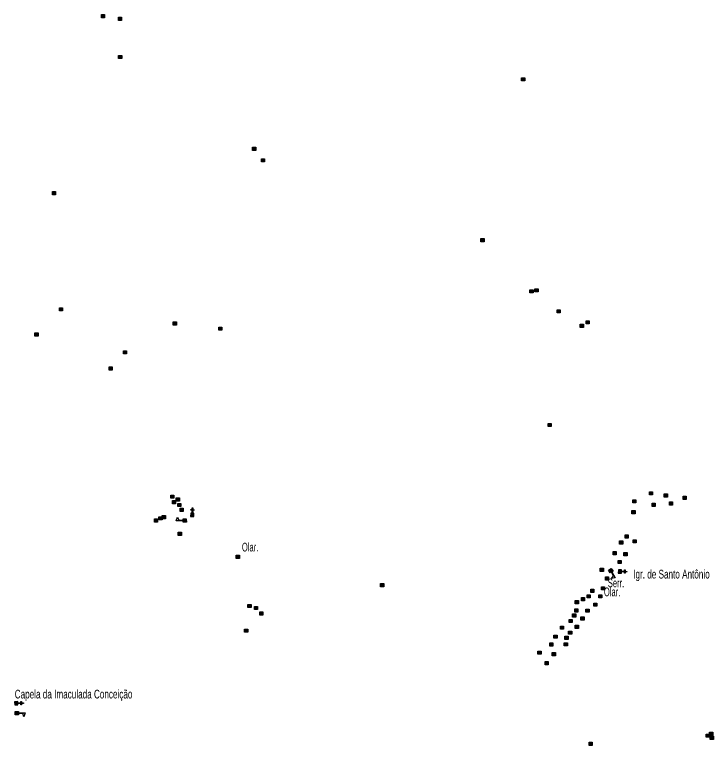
# Model space of a CAD drawing. Extents: x 647.8 to 672.9, y 6929.3 to 6957.3.
# Drawn here: x 653.69 to 660.11, y 6929.64 to 6936.36 of the extents above; entities that cross this region are included whole.
import ezdxf

# ---------------------------------------------------------------- set-up
doc = ezdxf.new("R2010")
doc.units = 0
doc.header["$LTSCALE"] = 0.032
for name, color, linetype, lineweight in [('2', 7, 'Continuous', 25), ('4', 7, 'Continuous', 25), ('6', 7, 'Continuous', 25)]:
    doc.layers.add(name, color=color, linetype=linetype, lineweight=lineweight)
doc.layers.add('61', color=7, linetype='Continuous')

msp = doc.modelspace()

# ---------------------------------------------------------------- hatches: boundary and pattern name
at = {"layer": '2'}
for points in [[(654.4867, 6936.3644), (654.5157, 6936.3644), (654.5157, 6936.3354), (654.4867, 6936.3354)], [(654.6425, 6936.3403), (654.6715, 6936.3403), (654.6715, 6936.3113), (654.6425, 6936.3113)], [(654.6447, 6935.9893), (654.6737, 6935.9893), (654.6737, 6935.9603), (654.6447, 6935.9603)], [(658.3501, 6935.7831), (658.3791, 6935.7831), (658.3791, 6935.7541), (658.3501, 6935.7541)], [(655.8776, 6935.1447), (655.9066, 6935.1447), (655.9066, 6935.1157), (655.8776, 6935.1157)], [(655.9588, 6935.0394), (655.9878, 6935.0394), (655.9878, 6935.0104), (655.9588, 6935.0104)], [(654.037, 6934.7366), (654.066, 6934.7366), (654.066, 6934.7076), (654.037, 6934.7076)], [(657.9771, 6934.3044), (658.0061, 6934.3044), (658.0061, 6934.2754), (657.9771, 6934.2754)], [(658.4729, 6933.8437), (658.5019, 6933.8437), (658.5019, 6933.8147), (658.4729, 6933.8147)], [(658.4269, 6933.8349), (658.4559, 6933.8349), (658.4559, 6933.8059), (658.4269, 6933.8059)], [(654.1006, 6933.6682), (654.1296, 6933.6682), (654.1296, 6933.6392), (654.1006, 6933.6392)], [(658.677, 6933.6507), (658.706, 6933.6507), (658.706, 6933.6217), (658.677, 6933.6217)], [(655.1471, 6933.5388), (655.1761, 6933.5388), (655.1761, 6933.5098), (655.1471, 6933.5098)], [(658.8898, 6933.5168), (658.9188, 6933.5168), (658.9188, 6933.4878), (658.8898, 6933.4878)], [(658.9446, 6933.5497), (658.9736, 6933.5497), (658.9736, 6933.5207), (658.9446, 6933.5207)], [(653.8746, 6933.4379), (653.9036, 6933.4379), (653.9036, 6933.4089), (653.8746, 6933.4089)], [(655.5661, 6933.4905), (655.5951, 6933.4905), (655.5951, 6933.4615), (655.5661, 6933.4615)], [(654.6886, 6933.2733), (654.7176, 6933.2733), (654.7176, 6933.2443), (654.6886, 6933.2443)], [(654.5569, 6933.1241), (654.5859, 6933.1241), (654.5859, 6933.0951), (654.5569, 6933.0951)], [(658.5936, 6932.6042), (658.6226, 6932.6042), (658.6226, 6932.5752), (658.5936, 6932.5752)], [(659.526, 6931.9768), (659.555, 6931.9768), (659.555, 6931.9478), (659.526, 6931.9478)], [(659.662, 6931.957), (659.691, 6931.957), (659.691, 6931.928), (659.662, 6931.928)], [(655.1251, 6931.946), (655.1541, 6931.946), (655.1541, 6931.917), (655.1251, 6931.917)], [(655.1405, 6931.8956), (655.1695, 6931.8956), (655.1695, 6931.8666), (655.1405, 6931.8666)], [(655.1756, 6931.9197), (655.2046, 6931.9197), (655.2046, 6931.8907), (655.1756, 6931.8907)], [(659.3724, 6931.9022), (659.4014, 6931.9022), (659.4014, 6931.8732), (659.3724, 6931.8732)], [(659.8353, 6931.9351), (659.8643, 6931.9351), (659.8643, 6931.9061), (659.8353, 6931.9061)], [(655.1888, 6931.8693), (655.2178, 6931.8693), (655.2178, 6931.8403), (655.1888, 6931.8403)], [(655.2107, 6931.8254), (655.2397, 6931.8254), (655.2397, 6931.7964), (655.2107, 6931.7964)], [(659.5501, 6931.8714), (659.5791, 6931.8714), (659.5791, 6931.8424), (659.5501, 6931.8424)], [(659.7103, 6931.8824), (659.7393, 6931.8824), (659.7393, 6931.8534), (659.7103, 6931.8534)], [(655.0462, 6931.7574), (655.0752, 6931.7574), (655.0752, 6931.7284), (655.0462, 6931.7284)], [(659.3658, 6931.8034), (659.3948, 6931.8034), (659.3948, 6931.7744), (659.3658, 6931.7744)], [(654.9738, 6931.7267), (655.0028, 6931.7267), (655.0028, 6931.6977), (654.9738, 6931.6977)], [(655.0154, 6931.7464), (655.0444, 6931.7464), (655.0444, 6931.7174), (655.0154, 6931.7174)], [(655.1931, 6931.6038), (655.2221, 6931.6038), (655.2221, 6931.5748), (655.1931, 6931.5748)], [(659.3022, 6931.5797), (659.3312, 6931.5797), (659.3312, 6931.5507), (659.3022, 6931.5507)], [(659.2518, 6931.5248), (659.2808, 6931.5248), (659.2808, 6931.4958), (659.2518, 6931.4958)], [(659.3768, 6931.5358), (659.4058, 6931.5358), (659.4058, 6931.5068), (659.3768, 6931.5068)], [(659.1925, 6931.4261), (659.2215, 6931.4261), (659.2215, 6931.3971), (659.1925, 6931.3971)], [(659.2916, 6931.4175), (659.3206, 6931.4175), (659.3206, 6931.3885), (659.2916, 6931.3885)], [(655.7263, 6931.3932), (655.7553, 6931.3932), (655.7553, 6931.3642), (655.7263, 6931.3642)], [(659.2386, 6931.3449), (659.2676, 6931.3449), (659.2676, 6931.3159), (659.2386, 6931.3159)], [(659.0741, 6931.2725), (659.1031, 6931.2725), (659.1031, 6931.2435), (659.0741, 6931.2435)], [(659.1223, 6931.1935), (659.1513, 6931.1935), (659.1513, 6931.1645), (659.1223, 6931.1645)], [(657.0535, 6931.1321), (657.0825, 6931.1321), (657.0825, 6931.1031), (657.0535, 6931.1031)], [(659.085, 6931.1036), (659.114, 6931.1036), (659.114, 6931.0746), (659.085, 6931.0746)], [(658.9534, 6931.029), (658.9824, 6931.029), (658.9824, 6931), (658.9534, 6931)], [(658.9863, 6931.0795), (659.0153, 6931.0795), (659.0153, 6931.0505), (658.9863, 6931.0505)], [(659.0609, 6931.029), (659.0899, 6931.029), (659.0899, 6931), (659.0609, 6931)], [(658.8437, 6930.9764), (658.8727, 6930.9764), (658.8727, 6930.9474), (658.8437, 6930.9474)], [(658.9007, 6931.0027), (658.9297, 6931.0027), (658.9297, 6930.9737), (658.9007, 6930.9737)], [(659.0148, 6930.9522), (659.0438, 6930.9522), (659.0438, 6930.9232), (659.0148, 6930.9232)], [(655.8337, 6930.9413), (655.8627, 6930.9413), (655.8627, 6930.9123), (655.8337, 6930.9123)], [(655.893, 6930.9215), (655.922, 6930.9215), (655.922, 6930.8925), (655.893, 6930.8925)], [(658.8393, 6930.8996), (658.8683, 6930.8996), (658.8683, 6930.8706), (658.8393, 6930.8706)], [(658.9424, 6930.8974), (658.9714, 6930.8974), (658.9714, 6930.8684), (658.9424, 6930.8684)], [(655.9434, 6930.8711), (655.9724, 6930.8711), (655.9724, 6930.8421), (655.9434, 6930.8421)], [(658.8196, 6930.8535), (658.8486, 6930.8535), (658.8486, 6930.8245), (658.8196, 6930.8245)], [(658.8964, 6930.825), (658.9254, 6930.825), (658.9254, 6930.796), (658.8964, 6930.796)], [(658.7867, 6930.803), (658.8157, 6930.803), (658.8157, 6930.774), (658.7867, 6930.774)], [(658.8437, 6930.7482), (658.8727, 6930.7482), (658.8727, 6930.7192), (658.8437, 6930.7192)], [(655.803, 6930.7131), (655.832, 6930.7131), (655.832, 6930.6841), (655.803, 6930.6841)], [(658.7077, 6930.7416), (658.7367, 6930.7416), (658.7367, 6930.7126), (658.7077, 6930.7126)], [(658.7823, 6930.6955), (658.8113, 6930.6955), (658.8113, 6930.6665), (658.7823, 6930.6665)], [(658.6485, 6930.6583), (658.6775, 6930.6583), (658.6775, 6930.6293), (658.6485, 6930.6293)], [(658.7494, 6930.6473), (658.7784, 6930.6473), (658.7784, 6930.6183), (658.7494, 6930.6183)], [(658.609, 6930.5859), (658.638, 6930.5859), (658.638, 6930.5569), (658.609, 6930.5569)], [(658.7428, 6930.588), (658.7718, 6930.588), (658.7718, 6930.559), (658.7428, 6930.559)], [(658.5015, 6930.5113), (658.5305, 6930.5113), (658.5305, 6930.4823), (658.5015, 6930.4823)], [(658.6331, 6930.4981), (658.6621, 6930.4981), (658.6621, 6930.4691), (658.6331, 6930.4691)], [(658.5673, 6930.4147), (658.5963, 6930.4147), (658.5963, 6930.3857), (658.5673, 6930.3857)], [(660.0481, 6929.7478), (660.0771, 6929.7478), (660.0771, 6929.7188), (660.0481, 6929.7188)], [(660.0788, 6929.7654), (660.1078, 6929.7654), (660.1078, 6929.7364), (660.0788, 6929.7364)], [(658.9709, 6929.6732), (658.9999, 6929.6732), (658.9999, 6929.6442), (658.9709, 6929.6442)], [(660.0854, 6929.7281), (660.1144, 6929.7281), (660.1144, 6929.6991), (660.0854, 6929.6991)]]:
    msp.add_hatch(color=256, dxfattribs=at).paths.add_polyline_path(points)
at = {"layer": '4'}
for points in [[(655.2679, 6931.6973), (655.2379, 6931.697), (655.2376, 6931.727), (655.2676, 6931.7273)], [(659.1759, 6931.2717), (659.1913, 6931.2459), (659.1655, 6931.2306), (659.1501, 6931.2564)], [(653.6935, 6929.9544), (653.7234, 6929.9549), (653.7239, 6929.9249), (653.6939, 6929.9244)]]:
    msp.add_hatch(color=256, dxfattribs=at).paths.add_polyline_path(points)
at = {"layer": '6'}
for points in [[(655.3251, 6931.7795), (655.3201, 6931.7797), (655.3216, 6931.8072), (655.309, 6931.8079), (655.3093, 6931.8129), (655.3218, 6931.8122), (655.3227, 6931.8297), (655.3277, 6931.8294), (655.3267, 6931.8119), (655.3393, 6931.8113), (655.339, 6931.8063), (655.3265, 6931.8069)], [(655.3076, 6931.7804), (655.3061, 6931.7505), (655.336, 6931.7489), (655.3375, 6931.7788)], [(659.2704, 6931.2582), (659.2404, 6931.2589), (659.2397, 6931.2289), (659.2697, 6931.2282)], [(659.27, 6931.2407), (659.2701, 6931.2457), (659.2976, 6931.2451), (659.2979, 6931.2576), (659.3029, 6931.2575), (659.3026, 6931.245), (659.3201, 6931.2446), (659.32, 6931.2396), (659.3025, 6931.24), (659.3022, 6931.2275), (659.2972, 6931.2276), (659.2975, 6931.2401)], [(653.7185, 6930.0468), (653.6885, 6930.0462), (653.6891, 6930.0162), (653.7191, 6930.0168)], [(653.7189, 6930.0293), (653.7188, 6930.0343), (653.7463, 6930.0348), (653.746, 6930.0473), (653.751, 6930.0474), (653.7513, 6930.0349), (653.7687, 6930.0352), (653.7688, 6930.0302), (653.7513, 6930.0299), (653.7516, 6930.0174), (653.7466, 6930.0173), (653.7463, 6930.0298)]]:
    msp.add_hatch(color=256, dxfattribs=at).paths.add_polyline_path(points)

# ---------------------------------------------------------------- linework, layer by layer
at = {"layer": '2'}
for points in [[(654.4867, 6936.3644), (654.5157, 6936.3644), (654.5157, 6936.3354), (654.4867, 6936.3354)], [(654.6425, 6936.3403), (654.6715, 6936.3403), (654.6715, 6936.3113), (654.6425, 6936.3113)], [(654.6447, 6935.9893), (654.6737, 6935.9893), (654.6737, 6935.9603), (654.6447, 6935.9603)], [(658.3501, 6935.7831), (658.3791, 6935.7831), (658.3791, 6935.7541), (658.3501, 6935.7541)], [(655.8776, 6935.1447), (655.9066, 6935.1447), (655.9066, 6935.1157), (655.8776, 6935.1157)], [(655.9588, 6935.0394), (655.9878, 6935.0394), (655.9878, 6935.0104), (655.9588, 6935.0104)], [(654.037, 6934.7366), (654.066, 6934.7366), (654.066, 6934.7076), (654.037, 6934.7076)], [(657.9771, 6934.3044), (658.0061, 6934.3044), (658.0061, 6934.2754), (657.9771, 6934.2754)], [(658.4729, 6933.8437), (658.5019, 6933.8437), (658.5019, 6933.8147), (658.4729, 6933.8147)], [(658.4269, 6933.8349), (658.4559, 6933.8349), (658.4559, 6933.8059), (658.4269, 6933.8059)], [(654.1006, 6933.6682), (654.1296, 6933.6682), (654.1296, 6933.6392), (654.1006, 6933.6392)], [(658.677, 6933.6507), (658.706, 6933.6507), (658.706, 6933.6217), (658.677, 6933.6217)], [(655.1471, 6933.5388), (655.1761, 6933.5388), (655.1761, 6933.5098), (655.1471, 6933.5098)], [(658.8898, 6933.5168), (658.9188, 6933.5168), (658.9188, 6933.4878), (658.8898, 6933.4878)], [(658.9446, 6933.5497), (658.9736, 6933.5497), (658.9736, 6933.5207), (658.9446, 6933.5207)], [(653.8746, 6933.4379), (653.9036, 6933.4379), (653.9036, 6933.4089), (653.8746, 6933.4089)], [(655.5661, 6933.4905), (655.5951, 6933.4905), (655.5951, 6933.4615), (655.5661, 6933.4615)], [(654.6886, 6933.2733), (654.7176, 6933.2733), (654.7176, 6933.2443), (654.6886, 6933.2443)], [(654.5569, 6933.1241), (654.5859, 6933.1241), (654.5859, 6933.0951), (654.5569, 6933.0951)], [(658.5936, 6932.6042), (658.6226, 6932.6042), (658.6226, 6932.5752), (658.5936, 6932.5752)], [(659.526, 6931.9768), (659.555, 6931.9768), (659.555, 6931.9478), (659.526, 6931.9478)], [(659.662, 6931.957), (659.691, 6931.957), (659.691, 6931.928), (659.662, 6931.928)], [(655.1251, 6931.946), (655.1541, 6931.946), (655.1541, 6931.917), (655.1251, 6931.917)], [(655.1405, 6931.8956), (655.1695, 6931.8956), (655.1695, 6931.8666), (655.1405, 6931.8666)], [(655.1756, 6931.9197), (655.2046, 6931.9197), (655.2046, 6931.8907), (655.1756, 6931.8907)], [(659.3724, 6931.9022), (659.4014, 6931.9022), (659.4014, 6931.8732), (659.3724, 6931.8732)], [(659.8353, 6931.9351), (659.8643, 6931.9351), (659.8643, 6931.9061), (659.8353, 6931.9061)], [(655.1888, 6931.8693), (655.2178, 6931.8693), (655.2178, 6931.8403), (655.1888, 6931.8403)], [(655.2107, 6931.8254), (655.2397, 6931.8254), (655.2397, 6931.7964), (655.2107, 6931.7964)], [(659.5501, 6931.8714), (659.5791, 6931.8714), (659.5791, 6931.8424), (659.5501, 6931.8424)], [(659.7103, 6931.8824), (659.7393, 6931.8824), (659.7393, 6931.8534), (659.7103, 6931.8534)], [(655.0462, 6931.7574), (655.0752, 6931.7574), (655.0752, 6931.7284), (655.0462, 6931.7284)], [(659.3658, 6931.8034), (659.3948, 6931.8034), (659.3948, 6931.7744), (659.3658, 6931.7744)], [(654.9738, 6931.7267), (655.0028, 6931.7267), (655.0028, 6931.6977), (654.9738, 6931.6977)], [(655.0154, 6931.7464), (655.0444, 6931.7464), (655.0444, 6931.7174), (655.0154, 6931.7174)], [(655.1931, 6931.6038), (655.2221, 6931.6038), (655.2221, 6931.5748), (655.1931, 6931.5748)], [(659.3022, 6931.5797), (659.3312, 6931.5797), (659.3312, 6931.5507), (659.3022, 6931.5507)], [(659.2518, 6931.5248), (659.2808, 6931.5248), (659.2808, 6931.4958), (659.2518, 6931.4958)], [(659.3768, 6931.5358), (659.4058, 6931.5358), (659.4058, 6931.5068), (659.3768, 6931.5068)], [(659.1925, 6931.4261), (659.2215, 6931.4261), (659.2215, 6931.3971), (659.1925, 6931.3971)], [(659.2916, 6931.4175), (659.3206, 6931.4175), (659.3206, 6931.3885), (659.2916, 6931.3885)], [(655.7263, 6931.3932), (655.7553, 6931.3932), (655.7553, 6931.3642), (655.7263, 6931.3642)], [(659.2386, 6931.3449), (659.2676, 6931.3449), (659.2676, 6931.3159), (659.2386, 6931.3159)], [(659.0741, 6931.2725), (659.1031, 6931.2725), (659.1031, 6931.2435), (659.0741, 6931.2435)], [(659.1223, 6931.1935), (659.1513, 6931.1935), (659.1513, 6931.1645), (659.1223, 6931.1645)], [(657.0535, 6931.1321), (657.0825, 6931.1321), (657.0825, 6931.1031), (657.0535, 6931.1031)], [(659.085, 6931.1036), (659.114, 6931.1036), (659.114, 6931.0746), (659.085, 6931.0746)], [(658.9534, 6931.029), (658.9824, 6931.029), (658.9824, 6931), (658.9534, 6931)], [(658.9863, 6931.0795), (659.0153, 6931.0795), (659.0153, 6931.0505), (658.9863, 6931.0505)], [(659.0609, 6931.029), (659.0899, 6931.029), (659.0899, 6931), (659.0609, 6931)], [(658.8437, 6930.9764), (658.8727, 6930.9764), (658.8727, 6930.9474), (658.8437, 6930.9474)], [(658.9007, 6931.0027), (658.9297, 6931.0027), (658.9297, 6930.9737), (658.9007, 6930.9737)], [(659.0148, 6930.9522), (659.0438, 6930.9522), (659.0438, 6930.9232), (659.0148, 6930.9232)], [(655.8337, 6930.9413), (655.8627, 6930.9413), (655.8627, 6930.9123), (655.8337, 6930.9123)], [(655.893, 6930.9215), (655.922, 6930.9215), (655.922, 6930.8925), (655.893, 6930.8925)], [(658.8393, 6930.8996), (658.8683, 6930.8996), (658.8683, 6930.8706), (658.8393, 6930.8706)], [(658.9424, 6930.8974), (658.9714, 6930.8974), (658.9714, 6930.8684), (658.9424, 6930.8684)], [(655.9434, 6930.8711), (655.9724, 6930.8711), (655.9724, 6930.8421), (655.9434, 6930.8421)], [(658.8196, 6930.8535), (658.8486, 6930.8535), (658.8486, 6930.8245), (658.8196, 6930.8245)], [(658.8964, 6930.825), (658.9254, 6930.825), (658.9254, 6930.796), (658.8964, 6930.796)], [(658.7867, 6930.803), (658.8157, 6930.803), (658.8157, 6930.774), (658.7867, 6930.774)], [(658.8437, 6930.7482), (658.8727, 6930.7482), (658.8727, 6930.7192), (658.8437, 6930.7192)], [(655.803, 6930.7131), (655.832, 6930.7131), (655.832, 6930.6841), (655.803, 6930.6841)], [(658.7077, 6930.7416), (658.7367, 6930.7416), (658.7367, 6930.7126), (658.7077, 6930.7126)], [(658.7823, 6930.6955), (658.8113, 6930.6955), (658.8113, 6930.6665), (658.7823, 6930.6665)], [(658.6485, 6930.6583), (658.6775, 6930.6583), (658.6775, 6930.6293), (658.6485, 6930.6293)], [(658.7494, 6930.6473), (658.7784, 6930.6473), (658.7784, 6930.6183), (658.7494, 6930.6183)], [(658.609, 6930.5859), (658.638, 6930.5859), (658.638, 6930.5569), (658.609, 6930.5569)], [(658.7428, 6930.588), (658.7718, 6930.588), (658.7718, 6930.559), (658.7428, 6930.559)], [(658.5015, 6930.5113), (658.5305, 6930.5113), (658.5305, 6930.4823), (658.5015, 6930.4823)], [(658.6331, 6930.4981), (658.6621, 6930.4981), (658.6621, 6930.4691), (658.6331, 6930.4691)], [(658.5673, 6930.4147), (658.5963, 6930.4147), (658.5963, 6930.3857), (658.5673, 6930.3857)], [(660.0481, 6929.7478), (660.0771, 6929.7478), (660.0771, 6929.7188), (660.0481, 6929.7188)], [(660.0788, 6929.7654), (660.1078, 6929.7654), (660.1078, 6929.7364), (660.0788, 6929.7364)], [(658.9709, 6929.6732), (658.9999, 6929.6732), (658.9999, 6929.6442), (658.9709, 6929.6442)], [(660.0854, 6929.7281), (660.1144, 6929.7281), (660.1144, 6929.6991), (660.0854, 6929.6991)]]:
    msp.add_lwpolyline(points, close=True, dxfattribs=at)
at = {"layer": '4'}
for p, q in [((655.2377, 6931.7095), (655.2377, 6931.7145)), ((659.1805, 6931.2395), (659.1762, 6931.237)), ((653.7236, 6929.9424), (653.7237, 6929.9374))]:
    msp.add_line(p, q, dxfattribs=at)
for points in [[(655.2377, 6931.7095), (655.1752, 6931.7088), (655.1874, 6931.7439), (655.1982, 6931.7141), (655.2377, 6931.7145)], [(655.2679, 6931.6973), (655.2379, 6931.697), (655.2376, 6931.727), (655.2676, 6931.7273)], [(659.1759, 6931.2717), (659.1913, 6931.2459), (659.1655, 6931.2306), (659.1501, 6931.2564)], [(659.1805, 6931.2395), (659.2125, 6931.1858), (659.176, 6931.1787), (659.1964, 6931.203), (659.1762, 6931.237)], [(653.6935, 6929.9544), (653.7234, 6929.9549), (653.7239, 6929.9249), (653.6939, 6929.9244)], [(653.7236, 6929.9424), (653.7861, 6929.9433), (653.7741, 6929.9081), (653.7632, 6929.938), (653.7237, 6929.9374)]]:
    msp.add_lwpolyline(points, close=True, dxfattribs=at)
at = {"layer": '6'}
for points in [[(655.3251, 6931.7795), (655.3201, 6931.7797), (655.3216, 6931.8072), (655.309, 6931.8079), (655.3093, 6931.8129), (655.3218, 6931.8122), (655.3227, 6931.8297), (655.3277, 6931.8294), (655.3267, 6931.8119), (655.3393, 6931.8113), (655.339, 6931.8063), (655.3265, 6931.8069)], [(655.3076, 6931.7804), (655.3061, 6931.7505), (655.336, 6931.7489), (655.3375, 6931.7788)], [(659.2704, 6931.2582), (659.2404, 6931.2589), (659.2397, 6931.2289), (659.2697, 6931.2282)], [(659.27, 6931.2407), (659.2701, 6931.2457), (659.2976, 6931.2451), (659.2979, 6931.2576), (659.3029, 6931.2575), (659.3026, 6931.245), (659.3201, 6931.2446), (659.32, 6931.2396), (659.3025, 6931.24), (659.3022, 6931.2275), (659.2972, 6931.2276), (659.2975, 6931.2401)], [(653.7185, 6930.0468), (653.6885, 6930.0462), (653.6891, 6930.0162), (653.7191, 6930.0168)], [(653.7189, 6930.0293), (653.7188, 6930.0343), (653.7463, 6930.0348), (653.746, 6930.0473), (653.751, 6930.0474), (653.7513, 6930.0349), (653.7687, 6930.0352), (653.7688, 6930.0302), (653.7513, 6930.0299), (653.7516, 6930.0174), (653.7466, 6930.0173), (653.7463, 6930.0298)]]:
    msp.add_lwpolyline(points, close=True, dxfattribs=at)

# ---------------------------------------------------------------- texts
at = {"layer": '61'}
for s, width, p in [('Olar.', 0.65, (655.7787, 6931.4274)), ('Igr. de Santo Antônio', 0.7, (659.3773, 6931.1788)), ('Serr.', 0.65, (659.1438, 6931.098)), ('Olar.', 0.65, (659.1078, 6931.0159)), ('Capela da Imaculada Conceição', 0.7, (653.6896, 6930.0757))]:
    msp.add_text(s, height=0.08, dxfattribs=dict(at, width=width)).set_placement(p)

doc.saveas('drawing.dxf')
